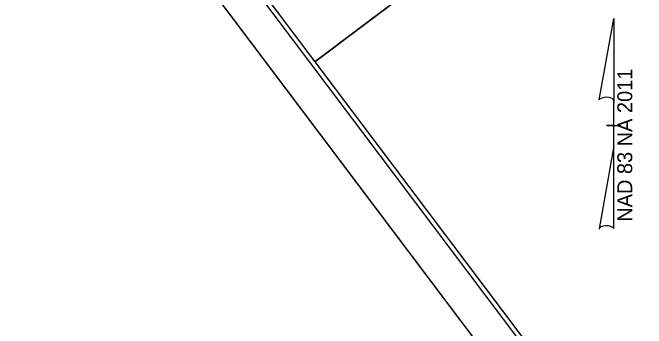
# Model space of a CAD drawing. Extents: x 1261689 to 1263694, y 776294 to 778298.
# Drawn here: x 1261806.3 to 1262167.1, y 777295.7 to 777475.5 of the extents above; entities that cross this region are included whole.
import ezdxf

# ---------------------------------------------------------------- set-up
doc = ezdxf.new("R2010")
doc.units = 0
for name, color, linetype in [('Old_Level_1', 7, 'Continuous'), ('Sheet Clip Boundary CELL', 7, 'Continuous'), ('Sheet Cutting Line CELL', 7, 'Continuous'), ('Sheet Layout Plan Border', 7, 'Continuous'), ('Sheet Plan CELL', 7, 'Continuous'), ('Sheet Plan Layout CELL', 7, 'Continuous'), ('Sheet Plot Border Inside CELL', 7, 'Continuous'), ('Sheet Plot Border Outside CELL', 7, 'Continuous')]:
    doc.layers.add(name, color=color, linetype=linetype)

msp = doc.modelspace()

# ---------------------------------------------------------------- linework, layer by layer
at = {"layer": 'Old_Level_1'}
for p, q in [((1262140.34, 777425.85), (1262148.56, 777472.2)), ((1262148.61, 777472.2), (1262148.56, 777472.2)), ((1262148.61, 777472.2), (1262148.56, 777472.2)), ((1262148.61, 777472.2), (1262148.59, 777424.4)), ((1262148.58, 777399.6), (1262148.59, 777425.8)), ((1262148.59, 777424.4), (1262148.59, 777425.75)), ((1262144.58, 777411.2), (1262144.53, 777411.2)), ((1262148.13, 777411.2), (1262144.58, 777411.2)), ((1262144.63, 777411.2), (1262152.63, 777411.2)), ((1262148.58, 777399.6), (1262140.21, 777352.35)), ((1262148.61, 777352.55), (1262148.58, 777399.6))]:
    msp.add_line(p, q, dxfattribs=at)
for centre, start_param, end_param in [((1262144.47, 777425.36), 0.216388, 2.908219), ((1262144.44, 777352.19), 0.201328, 3.141593)]:
    msp.add_ellipse(centre, major_axis=(4.23, -0.03), ratio=0.461098, start_param=start_param, end_param=end_param, dxfattribs=at)
at = {"layer": 'Sheet Clip Boundary CELL'}
msp.add_lwpolyline([(1263412.02, 777289.49), (1262673.2, 778270.38), (1262003.42, 777765.91), (1262147.38, 777574.78), (1261978.45, 777447.54), (1262573.31, 776657.77)], close=True, dxfattribs=at)
at = {"layer": 'Sheet Cutting Line CELL'}
msp.add_line((1261806.31, 777638.71), (1262819.17, 776293.98), dxfattribs=at)
at = {"layer": 'Sheet Layout Plan Border'}
msp.add_lwpolyline([(1263545.59, 777112.15), (1262703.29, 778230.44), (1262033.51, 777725.96), (1262147.38, 777574.78), (1261978.45, 777447.54), (1262706.88, 776480.43)], close=True, dxfattribs=at)
at = {"layer": 'Sheet Plan CELL'}
msp.add_lwpolyline([(1261834.48, 777638.68), (1262736.97, 776440.49), (1263575.67, 777072.22), (1262673.2, 778270.38)], close=True, dxfattribs=at)
at = {"layer": 'Sheet Plan Layout CELL'}
for points in [[(1262737, 776440.49), (1263575.67, 777072.22), (1262673.21, 778270.37), (1262003.44, 777765.89), (1262147.38, 777574.78), (1261978.45, 777447.54)], [(1262147.38, 777574.78), (1262003.42, 777765.91), (1261834.48, 777638.69), (1261978.45, 777447.54)]]:
    msp.add_lwpolyline(points, close=True, dxfattribs=at)
at = {"layer": 'Sheet Plot Border Inside CELL'}
msp.add_lwpolyline([(1263670.02, 776951.13), (1262667.69, 778281.86), (1261824.99, 777647.14), (1262827.32, 776316.4)], close=True, dxfattribs=at)
at = {"layer": 'Sheet Plot Border Outside CELL'}
msp.add_lwpolyline([(1263693.82, 776952.78), (1262680.96, 778297.5), (1261806.31, 777638.71), (1262819.17, 776293.98)], close=True, dxfattribs=at)

# ---------------------------------------------------------------- texts
at = {"layer": 'Old_Level_1'}
msp.add_text('NAD 83 NA 2011', height=8.5, rotation=89.9761, dxfattribs=at).set_placement((1262159.08, 777356.45))

doc.saveas('drawing.dxf')
